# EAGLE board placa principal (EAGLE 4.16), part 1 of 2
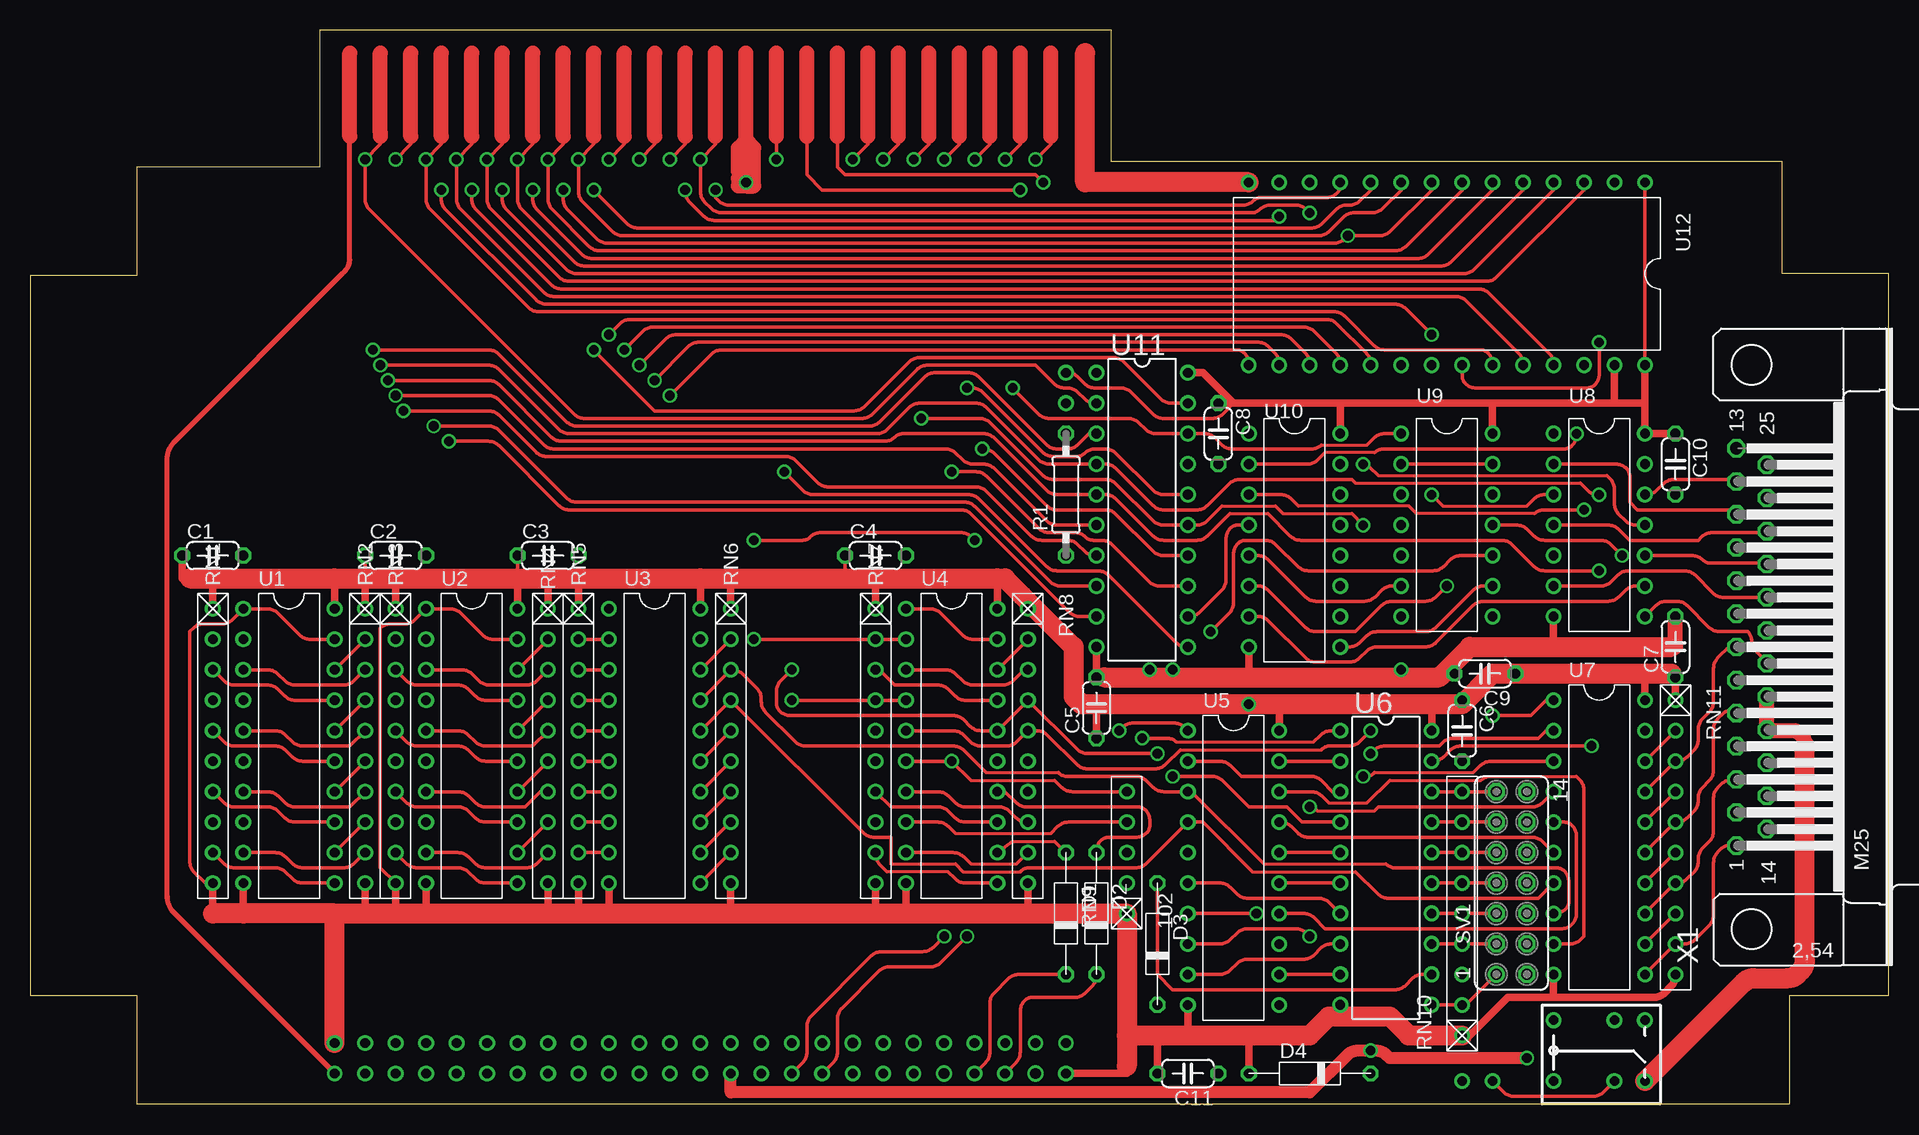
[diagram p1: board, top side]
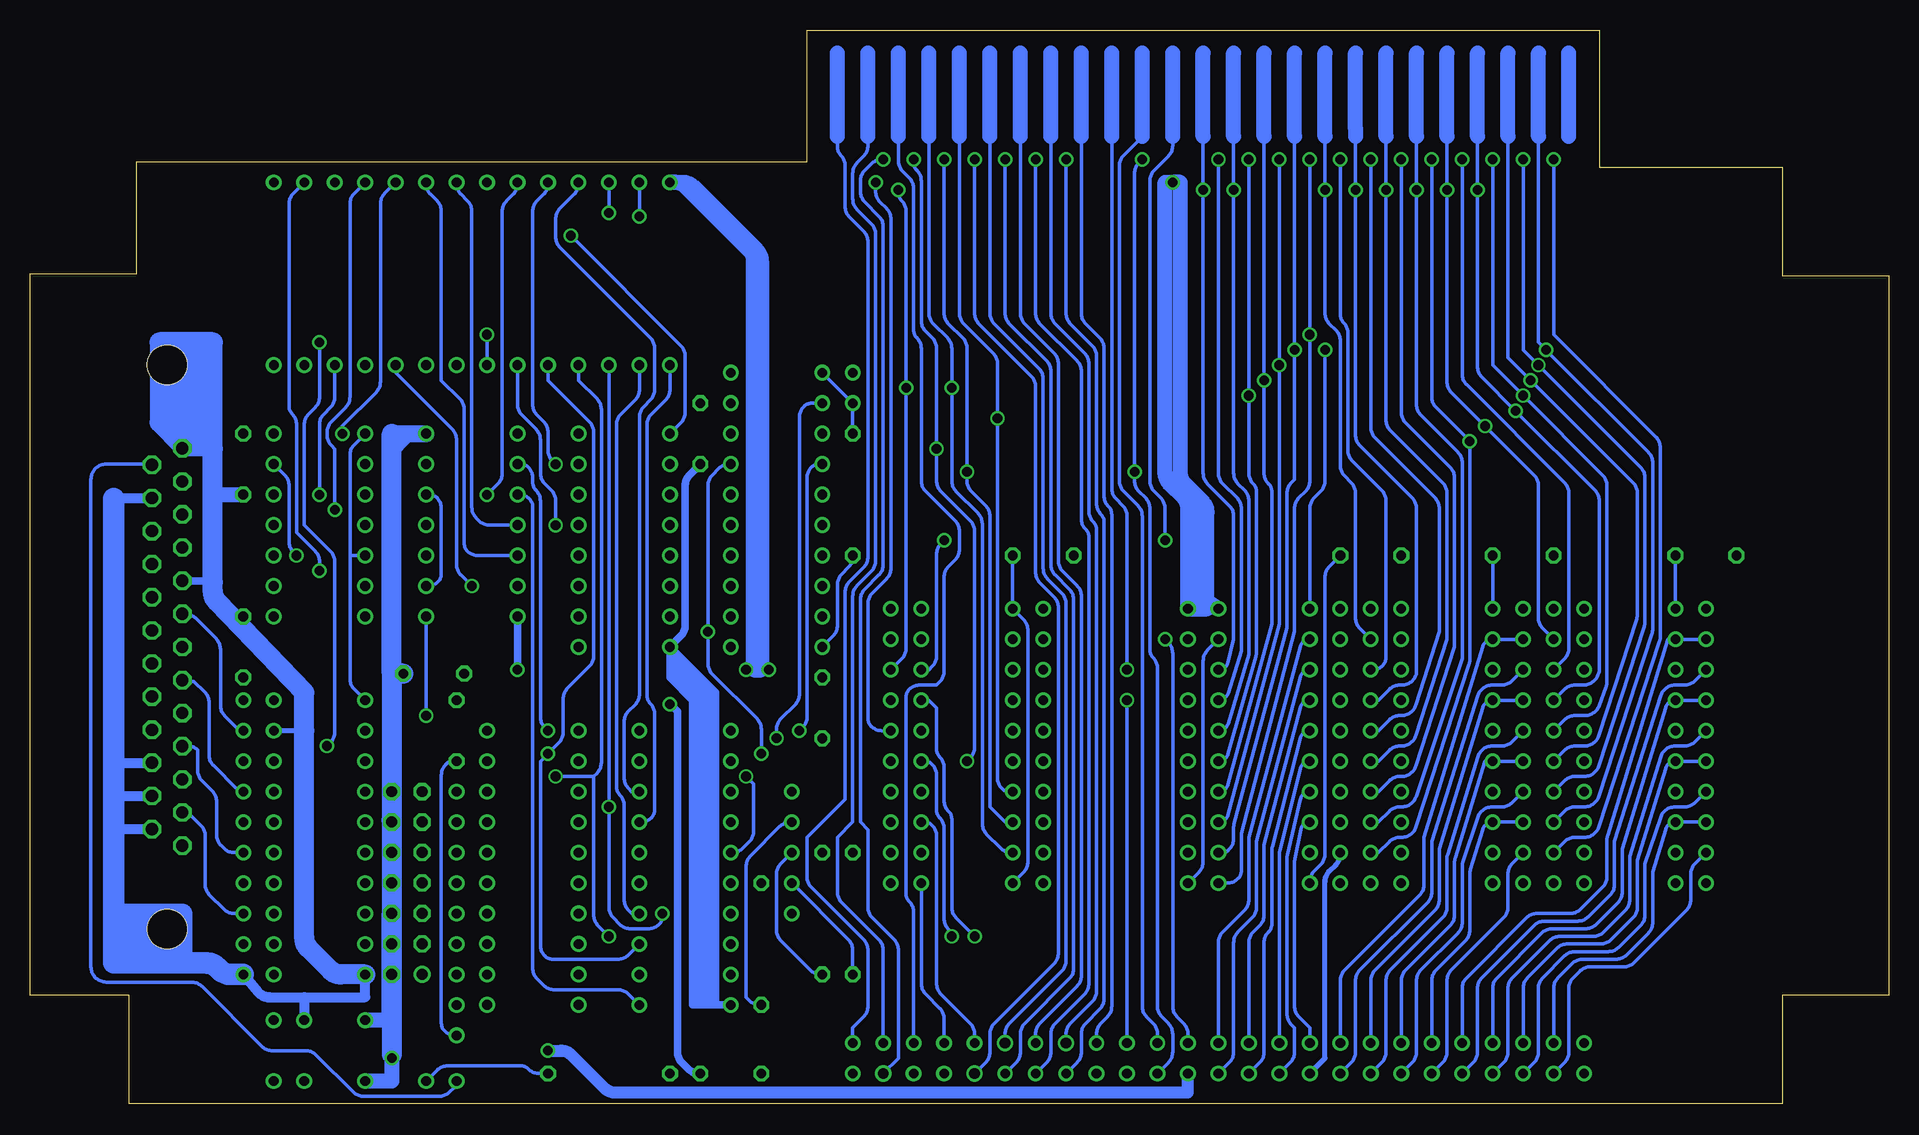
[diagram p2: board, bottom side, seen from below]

Size 154.94 x 89.53 mm. Coordinates in mm from the lower left corner, seen from the top.
Outline: 0,9.05 8.88,9.05 8.88,0 146.68,0 146.68,9.05 154.92,9.05 154.94,58.42 154.94,69.22 146.05,69.22 146.05,78.58 90.17,78.58 90.17,89.53 24.12,89.53 24.12,78.11 8.88,78.11 8.88,69.05 0,69.05 0,9.05
Copper layers (1*16): Top 0.035mm / dielectric 1.5mm / Bottom 0.035mm
Design rules "ITEADstudio_DRC": minimum track width 6mil, minimum drill 12mil, track to track 6mil, track to pad 6mil, pad to pad 6mil, via to via 6mil, smd to smd 0mil, copper to edge 10mil, drill to drill 10mil, minimum pad ring 10mil, minimum via ring 6mil, stop-mask expansion 2mil, vias tented up to drill 100mil, thermal gap 10mil

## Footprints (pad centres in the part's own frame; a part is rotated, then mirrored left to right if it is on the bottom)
1,27/0,8-REDONDO = drill 0.813 pad 1.27 round: 1 0,0
C050-024X044 = drill 0.813 octagon: 1 -2.54,0; 2 2.54,0
D-10/2 = drill 0.813 octagon: P$3 -5.08,0; P$4 5.08,0
0207/10 = drill 0.813 octagon: 1 -5.08,0; 2 5.08,0
RN-101 = drill 0.8 round: 1 -11.43,0; 2 -8.89,0; 3 -6.35,0; 4 -3.81,0; 5 -1.27,0; 6 1.27,0; 7 3.81,0; 8 6.35,0; 9 8.89,0; 10 11.43,0
R-51 = drill 0.8 round: 1 -5.08,0; 2 -2.54,0; 3 0,0; 4 2.54,0; 5 5.08,0
RN-91 = drill 0.8 round: 1 -10.16,0; 2 -7.62,0; 3 -5.08,0; 4 -2.54,0; 5 0,0; 6 2.54,0; 7 5.08,0; 8 7.62,0; 9 10.16,0
FE07-2 = drill 0.914 round: 1 -7.62,1.27 | drill 0.914 octagon: 2 -7.62,-1.27; 3 -5.08,1.27; 4 -5.08,-1.27; 5 -2.54,1.27; 6 -2.54,-1.27; 7 0,1.27; 8 0,-1.27; 9 2.54,1.27; 10 2.54,-1.27; 11 5.08,1.27; 12 5.08,-1.27; 13 7.62,1.27; 14 7.62,-1.27
DIL20-B = drill 0.8 round: 1 -11.43,-3.81; 2 -8.89,-3.81; 3 -6.35,-3.81; 4 -3.81,-3.81; 5 -1.27,-3.81; 6 1.27,-3.81; 7 3.81,-3.81; 8 6.35,-3.81; 9 8.89,-3.81; 10 11.43,-3.81; 11 11.43,3.81; 12 8.89,3.81; 13 6.35,3.81; 14 3.81,3.81; 15 1.27,3.81; 16 -1.27,3.81; 17 -3.81,3.81; 18 -6.35,3.81; 19 -8.89,3.81; 20 -11.43,3.81
DIL20 = drill 0.813 round: 1 -11.43,-3.81; 2 -8.89,-3.81; 3 -6.35,-3.81; 4 -3.81,-3.81; 5 -1.27,-3.81; 6 1.27,-3.81; 7 3.81,-3.81; 8 6.35,-3.81; 9 8.89,-3.81; 10 11.43,-3.81; 11 11.43,3.81; 12 8.89,3.81; 13 6.35,3.81; 14 3.81,3.81; 15 1.27,3.81; 16 -1.27,3.81; 17 -3.81,3.81; 18 -6.35,3.81; 19 -8.89,3.81; 20 -11.43,3.81
DIL14-B = drill 0.813 round: 1 -7.62,-3.81; 2 -5.08,-3.81; 3 -2.54,-3.81; 4 0,-3.81; 5 2.54,-3.81; 6 5.08,-3.81; 7 7.62,-3.81; 8 7.62,3.81; 9 5.08,3.81; 10 2.54,3.81; 11 0,3.81; 12 -2.54,3.81; 13 -5.08,3.81; 14 -7.62,3.81
DIL16-B = drill 0.813 round: 1 -8.89,-3.81; 2 -6.35,-3.81; 3 -3.81,-3.81; 4 -1.27,-3.81; 5 1.27,-3.81; 6 3.81,-3.81; 7 6.35,-3.81; 8 8.89,-3.81; 9 8.89,3.81; 10 6.35,3.81; 11 3.81,3.81; 12 1.27,3.81; 13 -1.27,3.81; 14 -3.81,3.81; 15 -6.35,3.81; 16 -8.89,3.81
DIL28-6B = drill 0.8 round: 1 -16.51,-7.62; 2 -13.97,-7.62; 3 -11.43,-7.62; 4 -8.89,-7.62; 5 -6.35,-7.62; 6 -3.81,-7.62; 7 -1.27,-7.62; 8 1.27,-7.62; 9 3.81,-7.62; 10 6.35,-7.62; 11 8.89,-7.62; 12 11.43,-7.62; 13 13.97,-7.62; 14 16.51,-7.62; 15 16.51,7.62; 16 13.97,7.62; 17 11.43,7.62; 18 8.89,7.62; 19 6.35,7.62; 20 3.81,7.62; 21 1.27,7.62; 22 -1.27,7.62; 23 -3.81,7.62; 24 -6.35,7.62; 25 -8.89,7.62; 26 -11.43,7.62; 27 -13.97,7.62; 28 -16.51,7.62
M25H = drill 1.016 octagon: 1 -16.561,1.27; 2 -13.792,1.27; 3 -11.049,1.27; 4 -8.28,1.27; 5 -5.512,1.27; 6 -2.769,1.27; 7 0,1.27; 8 2.769,1.27; 9 5.512,1.27; 10 8.28,1.27; 11 11.049,1.27; 12 13.792,1.27; 13 16.561,1.27; 14 -15.189,-1.27; 15 -12.421,-1.27; 16 -9.652,-1.27; 17 -6.909,-1.27; 18 -4.14,-1.27; 19 -1.372,-1.27; 20 1.372,-1.27; 21 4.14,-1.27; 22 6.909,-1.27; 23 9.652,-1.27; 24 12.421,-1.27; 25 15.189,-1.27 | hole 3.302: 23.52,0; -23.52,0

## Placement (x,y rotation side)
1  1,27-REDONDO0.8  [1,27/0,8-REDONDO]  132.08,1.91 0 top
2  1,27-REDONDO0.8  [1,27/0,8-REDONDO]  132.08,6.99 0 top
2-GND  1,27-REDONDO0.8  [1,27/0,8-REDONDO]  25.39,5.08 0 top
3-A15  1,27-REDONDO0.8  [1,27/0,8-REDONDO]  27.94,2.54 180 top
4  1,27-REDONDO0.8  [1,27/0,8-REDONDO]  86.36,58.42 0 top
4-A14  1,27-REDONDO0.8  [1,27/0,8-REDONDO]  27.94,5.08 0 top
5-A13  1,27-REDONDO0.8  [1,27/0,8-REDONDO]  30.48,2.54 180 top
6-A12  1,27-REDONDO0.8  [1,27/0,8-REDONDO]  30.48,5.08 0 top
7-A11  1,27-REDONDO0.8  [1,27/0,8-REDONDO]  33.02,2.54 180 top
8-A10  1,27-REDONDO0.8  [1,27/0,8-REDONDO]  33.02,5.08 0 top
9-A9  1,27-REDONDO0.8  [1,27/0,8-REDONDO]  35.55,2.54 180 top
10-A8  1,27-REDONDO0.8  [1,27/0,8-REDONDO]  35.55,5.08 0 top
11-A7  1,27-REDONDO0.8  [1,27/0,8-REDONDO]  38.09,2.54 180 top
12-A6  1,27-REDONDO0.8  [1,27/0,8-REDONDO]  38.09,5.08 0 top
13-A5  1,27-REDONDO0.8  [1,27/0,8-REDONDO]  40.63,2.54 180 top
14-A4  1,27-REDONDO0.8  [1,27/0,8-REDONDO]  40.63,5.08 0 top
15-A3  1,27-REDONDO0.8  [1,27/0,8-REDONDO]  43.17,2.54 180 top
16-A2  1,27-REDONDO0.8  [1,27/0,8-REDONDO]  43.17,5.08 0 top
17-A1  1,27-REDONDO0.8  [1,27/0,8-REDONDO]  45.71,2.54 180 top
18-A0  1,27-REDONDO0.8  [1,27/0,8-REDONDO]  45.71,5.08 0 top
19-D7  1,27-REDONDO0.8  [1,27/0,8-REDONDO]  48.25,2.54 180 top
20-D6  1,27-REDONDO0.8  [1,27/0,8-REDONDO]  48.25,5.08 0 top
21-D5  1,27-REDONDO0.8  [1,27/0,8-REDONDO]  50.79,2.54 180 top
22-D4  1,27-REDONDO0.8  [1,27/0,8-REDONDO]  50.79,5.08 0 top
23-D3  1,27-REDONDO0.8  [1,27/0,8-REDONDO]  53.34,2.54 180 top
24-D2  1,27-REDONDO0.8  [1,27/0,8-REDONDO]  53.34,5.08 0 top
25-D1  1,27-REDONDO0.8  [1,27/0,8-REDONDO]  55.88,2.54 180 top
26-D0  1,27-REDONDO0.8  [1,27/0,8-REDONDO]  55.88,5.08 0 top
27-VCC  1,27-REDONDO0.8  [1,27/0,8-REDONDO]  58.41,2.54 180 top
28-MREQ  1,27-REDONDO0.8  [1,27/0,8-REDONDO]  58.41,5.08 0 top
29-M1  1,27-REDONDO0.8  [1,27/0,8-REDONDO]  60.95,2.54 180 top
31-IORQ  1,27-REDONDO0.8  [1,27/0,8-REDONDO]  63.49,2.54 180 top
32-RD  1,27-REDONDO0.8  [1,27/0,8-REDONDO]  63.49,5.08 0 top
33-WR  1,27-REDONDO0.8  [1,27/0,8-REDONDO]  66.04,2.54 180 top
42-ROMEN  1,27-REDONDO0.8  [1,27/0,8-REDONDO]  76.2,5.08 0 top
43-ROMDIS  1,27-REDONDO0.8  [1,27/0,8-REDONDO]  78.73,2.54 180 top
44-RAMRD  1,27-REDONDO0.8  [1,27/0,8-REDONDO]  78.73,5.08 0 top
45-RAMDIS  1,27-REDONDO0.8  [1,27/0,8-REDONDO]  81.28,2.54 180 top
49-GND  1,27-REDONDO0.8  [1,27/0,8-REDONDO]  86.36,2.54 180 top
64  1,27-REDONDO0.8  [1,27/0,8-REDONDO]  86.36,60.96 0 top
C1  [C050-024X044]  15.23,45.72 0 top
C2  [C050-024X044]  30.48,45.72 0 top
C3  [C050-024X044]  43.17,45.72 0 top
C4  [C050-024X044]  70.48,45.72 0 top
C5  [C050-024X044]  88.9,33.02 90 top
C6  [C050-024X044]  119.38,31.11 270 top
C7  [C050-024X044]  137.16,38.1 90 top
C8  [C050-024X044]  99.06,55.88 270 top
C9  [C050-024X044]  121.28,35.88 180 top
C10  [C050-024X044]  137.16,53.34 270 top
C11  100nF  [C050-024X044]  96.52,2.54 180 top
D1  [D-10/2]  86.36,15.88 270 top
D2  [D-10/2]  88.9,15.88 270 top
D3  [D-10/2]  93.98,13.34 270 top
D4  [D-10/2]  106.68,2.54 0 top
EX  1,27-REDONDO0.8  [1,27/0,8-REDONDO]  121.92,1.91 0 top
O  1,27-REDONDO0.8  [1,27/0,8-REDONDO]  134.62,1.91 0 top
P  1,27-REDONDO0.8  [1,27/0,8-REDONDO]  127,1.91 0 top
P@  1,27-REDONDO0.8  [1,27/0,8-REDONDO]  127,6.99 0 bottom
R1  1K  [0207/10]  86.36,50.8 90 top
RN1  [RN-101]  15.23,29.84 270 top
RN2  [RN-101]  27.94,29.84 270 top
RN3  [RN-101]  30.48,29.84 270 top
RN4  [RN-101]  43.17,29.84 270 top
RN5  102  [RN-101]  45.71,29.84 270 top
RN6  102  [RN-101]  58.41,29.84 270 top
RN7  [RN-101]  70.48,29.84 270 top
RN8  [RN-101]  83.18,29.84 270 top
RN9  102  [R-51]  91.44,20.95 90 top
RN10  102  [RN-91]  119.38,15.88 90 top
RN11  [RN-101]  137.16,22.23 270 top
S  1,27-REDONDO0.8  [1,27/0,8-REDONDO]  134.62,6.99 0 top
SV1  [FE07-2]  123.5,18.41 90 top
T  1,27-REDONDO0.8  [1,27/0,8-REDONDO]  119.38,1.91 0 top
U1  74LS244B  [DIL20-B]  21.59,29.84 270 top
U2  74LS244B  [DIL20-B]  36.82,29.84 270 top
U3  74LS245B  [DIL20-B]  52.06,29.84 270 top
U4  74LS244B  [DIL20-B]  76.83,29.84 270 top
U5  74HCT377B  [DIL20-B]  100.33,19.68 270 top
U6  GAL16V8  [DIL20]  113.03,19.68 270 top
U7  74LS245B  [DIL20-B]  130.81,22.23 270 top
U8  74LS07B  [DIL14-B]  130.81,48.26 270 top
U9  74HCT32B  [DIL14-B]  118.11,48.26 270 top
U10  74LS138B  [DIL16-B]  105.41,46.99 270 top
U11  GAL16V8-20  [DIL20]  92.7,49.53 270 top
U12  27128B  [DIL28-6B]  118.11,69.22 180 top
X1  [M25H]  143.5,38.1 90 top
